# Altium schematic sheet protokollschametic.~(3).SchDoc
size A4; PageSetup: Record=PageOptions|CenterHorizontal=True|CenterVertical=True|PrintScale=0.87|XCorrection=1.00|YCorrection=1.00|PrintKind=2|BorderSize=5000000|LeftOffset=0|BottomOffset=0|Orientation=2|PaperLength=1000|PaperWidth=1000|Scale=100|PaperSource=7|PrintQuality=-4|MediaType=1|DitherType=10|PaperKind=Letter|PrintScaleMode=1
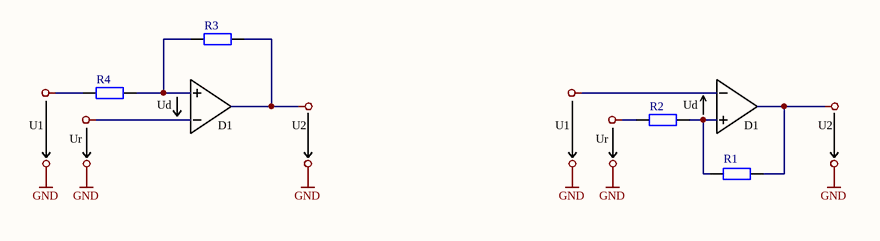
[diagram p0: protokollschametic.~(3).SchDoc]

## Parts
R1  Res2  [AXIAL-0.4]  (value not drawn)
R2  Res2  [AXIAL-0.4]  (value not drawn)
R3  Res2  [AXIAL-0.4]  (value not drawn)
R4  Res2  [AXIAL-0.4]  (value not drawn)

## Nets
GND: R1.2 R2.1 R3.2 R4.1
NetR1_1: R1.1 R2.2
NetR3_1: R3.1 R4.2

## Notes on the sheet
- (near R4) Ud
- (near R2) Ud
- U1
- (near R4) Ur
- D1
- U2
- (near R2) Ur
- (near R1) D1

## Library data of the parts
R1-R4 = Res2: Resistor; Value: 1K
